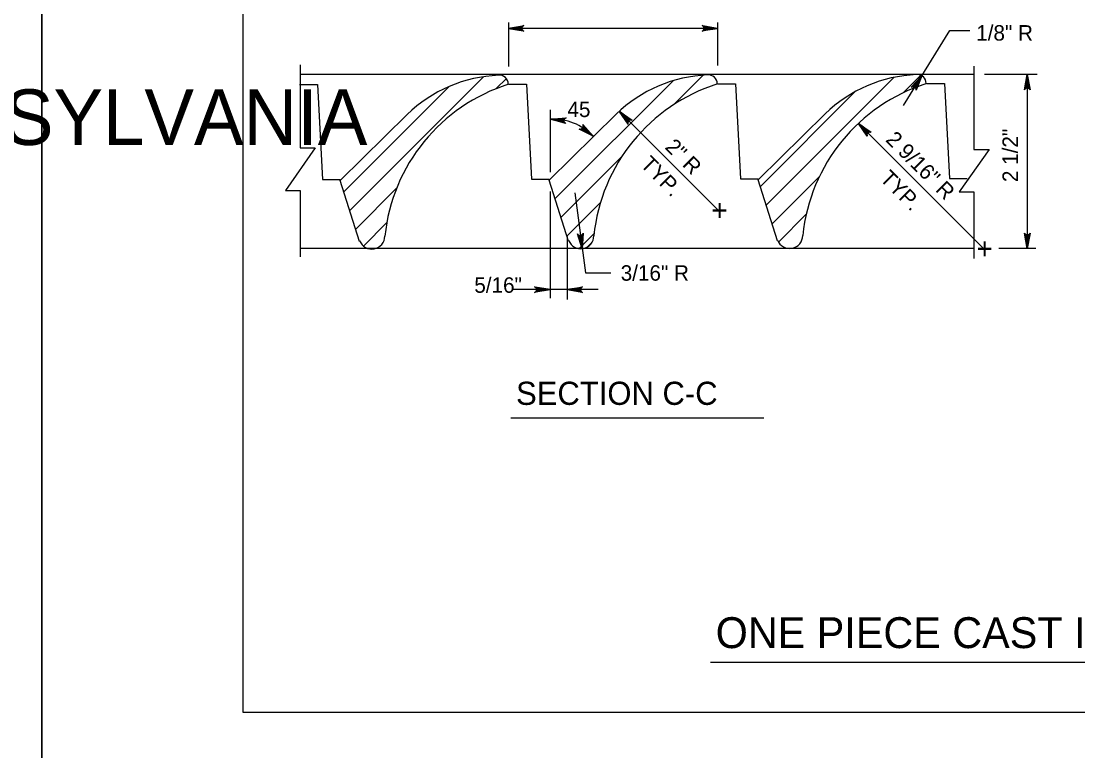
# Model space of a CAD drawing. Extents: x 2087776 to 2104538, y 970919 to 982612.
# Drawn here: x 2096040 to 2096713, y 976790 to 977255 of the extents above; entities that cross this region are included whole.
import ezdxf

# ---------------------------------------------------------------- set-up
doc = ezdxf.new("R2010")
doc.units = 0
doc.layers.add('1', color=7, linetype='Continuous')
doc.layers.add('PLT-BNDY', color=7, linetype='Continuous')

msp = doc.modelspace()

# ---------------------------------------------------------------- linework, layer by layer
at = {"layer": '1'}
for p, q in [((2096350.27, 977254.4), (2096350.27, 977226.29)), ((2096483.33, 977254.4), (2096483.33, 977226.92)), ((2096483.33, 977250.64), (2096350.27, 977250.64)), ((2096601.71, 977201.5), (2096631.33, 977249.24)), ((2096631.33, 977249.24), (2096644.03, 977249.24)), ((2096217.59, 977227.47), (2096217.59, 977174.47)), ((2096646.6, 977221.2), (2096217.59, 977221.2)), ((2096646.6, 977226.5), (2096646.6, 977173.5)), ((2096686.82, 977221.2), (2096653.44, 977221.2)), ((2096680.6, 977221.2), (2096680.6, 977110.47)), ((2096217.22, 977214.82), (2096228.75, 977214.82)), ((2096228.75, 977214.82), (2096231.93, 977154.35)), ((2096350.27, 977215.01), (2096361.81, 977215.03)), ((2096361.81, 977215.03), (2096364.99, 977154.55)), ((2096483.33, 977215.22), (2096494.86, 977215.22)), ((2096494.86, 977215.22), (2096498.05, 977154.76)), ((2096616.39, 977215.42), (2096627.91, 977215.43)), ((2096627.91, 977215.43), (2096631.1, 977154.96)), ((2096243.2, 977153.8), (2096285.8, 977195.79)), ((2096376.25, 977154), (2096418.85, 977196.01)), ((2096376.73, 977198.79), (2096376.73, 977158.95)), ((2096420.83, 977197.86), (2096483.79, 977134.89)), ((2096509.31, 977154.21), (2096551.9, 977196.21)), ((2096573.08, 977190.11), (2096652.26, 977110.93)), ((2096227.23, 977174.47), (2096208.21, 977147.38)), ((2096217.59, 977174.47), (2096227.23, 977174.47)), ((2096656.25, 977173.5), (2096637.23, 977146.42)), ((2096646.6, 977173.5), (2096656.25, 977173.5)), ((2096231.93, 977154.35), (2096243.2, 977154.35)), ((2096255.52, 977114.88), (2096243.2, 977153.8)), ((2096364.99, 977154.55), (2096376.25, 977154.55)), ((2096388.58, 977115.08), (2096376.25, 977154)), ((2096498.05, 977154.76), (2096509.31, 977154.76)), ((2096521.63, 977115.28), (2096509.31, 977154.21)), ((2096631.1, 977154.96), (2096642.37, 977154.96)), ((2096208.21, 977147.38), (2096217.59, 977147.38)), ((2096217.59, 977147.38), (2096217.59, 977105.07)), ((2096376.73, 977146.66), (2096376.73, 977078.76)), ((2096637.23, 977146.42), (2096646.6, 977146.42)), ((2096646.6, 977146.42), (2096646.6, 977104.11)), ((2096392.57, 977145.76), (2096399.29, 977094.93)), ((2096483.79, 977134.89), (2096483.79, 977134.89)), ((2096387.64, 977118.03), (2096387.64, 977077.86)), ((2096646.6, 977110.47), (2096217.59, 977110.47)), ((2096652.61, 977110.47), (2096652.61, 977110.47)), ((2096686, 977110.47), (2096662.49, 977110.47)), ((2096399.29, 977094.93), (2096415.46, 977094.93)), ((2096407.44, 977084.21), (2096352.36, 977084.21)), ((2096351.84, 977002.5), (2096512.91, 977002.5)), ((2096478.9, 976846.96), (2097073.31, 976846.96))]:
    msp.add_line(p, q, dxfattribs=at)
for points in [[(2098759.93, 976815.01), (2098759.93, 978665.4), (2096181.19, 978665.4), (2096181.19, 976815.01), (2098759.93, 976815.01), (2098759.93, 976901.49), (2098103.76, 976901.49), (2098103.76, 977113.68), (2098759.93, 977113.68), (2098759.93, 977208.71), (2098103.76, 977208.71), (2098103.76, 976815.01), (2098362.29, 976815.01), (2098362.29, 976901.49), (2098362.29, 976815.01), (2098614.92, 976815.01), (2098614.92, 976901.49), (2098614.92, 976861.08), (2098759.93, 976861.08)], [(2096350.27, 977250.64), (2096360.06, 977252.47), (2096359.68, 977252.21), (2096359.3, 977251.95), (2096359.11, 977251.62), (2096358.91, 977251.29), (2096358.86, 977250.97), (2096358.8, 977250.64), (2096358.86, 977250.31), (2096358.91, 977249.98), (2096359.11, 977249.65), (2096359.3, 977249.33), (2096359.68, 977249.06), (2096360.06, 977248.8), (2096350.27, 977250.64), (2096359.68, 977249.06), (2096359.3, 977249.33), (2096350.27, 977250.64), (2096359.11, 977249.65), (2096358.91, 977249.98), (2096350.27, 977250.64), (2096358.86, 977250.31), (2096358.8, 977250.64), (2096350.27, 977250.64), (2096358.86, 977250.97), (2096358.91, 977251.29), (2096350.27, 977250.64), (2096359.11, 977251.62), (2096359.3, 977251.95), (2096350.27, 977250.64), (2096359.68, 977252.21)], [(2096483.33, 977250.64), (2096473.55, 977248.8), (2096473.93, 977249.06), (2096474.3, 977249.33), (2096474.5, 977249.65), (2096474.69, 977249.98), (2096474.75, 977250.31), (2096474.8, 977250.64), (2096474.75, 977250.97), (2096474.69, 977251.29), (2096474.5, 977251.62), (2096474.3, 977251.95), (2096473.93, 977252.21), (2096473.55, 977252.47), (2096483.33, 977250.64), (2096473.93, 977252.21), (2096474.3, 977251.95), (2096483.33, 977250.64), (2096474.5, 977251.62), (2096474.69, 977251.29), (2096483.33, 977250.64), (2096474.75, 977250.97), (2096474.8, 977250.64), (2096483.33, 977250.64), (2096474.75, 977250.31), (2096474.69, 977249.98), (2096483.33, 977250.64), (2096474.5, 977249.65), (2096474.3, 977249.33), (2096483.33, 977250.64), (2096473.93, 977249.06)], [(2096455.63, 977202.11), (2096474.32, 977220.81)], [(2096601.48, 977209.52), (2096612.75, 977220.79)], [(2096613.46, 977220.44), (2096609.86, 977211.16), (2096609.84, 977211.61), (2096609.82, 977212.07), (2096609.64, 977212.41), (2096609.46, 977212.75), (2096609.21, 977212.97), (2096608.96, 977213.19), (2096608.66, 977213.32), (2096608.35, 977213.44), (2096607.97, 977213.45), (2096607.59, 977213.46), (2096607.16, 977213.27), (2096606.74, 977213.09), (2096613.46, 977220.44), (2096607.16, 977213.27), (2096607.59, 977213.46), (2096613.46, 977220.44), (2096607.97, 977213.45), (2096608.35, 977213.44), (2096613.46, 977220.44), (2096608.66, 977213.32), (2096608.96, 977213.19), (2096613.46, 977220.44), (2096609.21, 977212.97), (2096609.46, 977212.75), (2096613.46, 977220.44), (2096609.64, 977212.41), (2096609.82, 977212.07), (2096613.46, 977220.44), (2096609.84, 977211.61)], [(2096680.6, 977221.2), (2096682.43, 977211.41), (2096682.17, 977211.79), (2096681.91, 977212.16), (2096681.58, 977212.36), (2096681.25, 977212.55), (2096680.93, 977212.61), (2096680.6, 977212.67), (2096680.27, 977212.61), (2096679.94, 977212.55), (2096679.61, 977212.36), (2096679.29, 977212.16), (2096679.02, 977211.79), (2096678.76, 977211.41), (2096680.6, 977221.2), (2096679.02, 977211.79), (2096679.29, 977212.16), (2096680.6, 977221.2), (2096679.61, 977212.36), (2096679.94, 977212.55), (2096680.6, 977221.2), (2096680.27, 977212.61), (2096680.6, 977212.67), (2096680.6, 977221.2), (2096680.93, 977212.61), (2096681.25, 977212.55), (2096680.6, 977221.2), (2096681.58, 977212.36), (2096681.91, 977212.16), (2096680.6, 977221.2), (2096682.17, 977211.79)], [(2096245.49, 977146.58), (2096312.55, 977213.63)], [(2096249.26, 977134.67), (2096334.42, 977219.85)], [(2096342.45, 977212.22), (2096348.91, 977218.67)], [(2096380.01, 977142.15), (2096455.16, 977217.3)], [(2096514.4, 977138.1), (2096595.7, 977219.4)], [(2096510.64, 977150), (2096570.89, 977210.24)], [(2096377.05, 977192.71), (2096386.95, 977193.73), (2096386.56, 977193.5), (2096386.16, 977193.27), (2096385.94, 977192.96), (2096385.72, 977192.65), (2096385.64, 977192.33), (2096385.55, 977192.01), (2096385.58, 977191.67), (2096385.61, 977191.34), (2096385.78, 977191), (2096385.94, 977190.66), (2096386.3, 977190.37), (2096386.65, 977190.07), (2096377.05, 977192.71), (2096386.3, 977190.37), (2096385.94, 977190.66), (2096377.05, 977192.71), (2096385.78, 977191), (2096385.61, 977191.34), (2096377.05, 977192.71), (2096385.58, 977191.67), (2096385.55, 977192.01), (2096377.05, 977192.71), (2096385.64, 977192.33), (2096385.72, 977192.65), (2096377.05, 977192.71), (2096385.94, 977192.96), (2096386.16, 977193.27), (2096377.05, 977192.71), (2096386.56, 977193.5)], [(2096420.83, 977197.86), (2096429.04, 977192.24), (2096428.59, 977192.32), (2096428.14, 977192.4), (2096427.77, 977192.31), (2096427.4, 977192.21), (2096427.13, 977192.02), (2096426.86, 977191.83), (2096426.67, 977191.56), (2096426.47, 977191.29), (2096426.38, 977190.92), (2096426.29, 977190.55), (2096426.37, 977190.1), (2096426.45, 977189.64), (2096420.83, 977197.86), (2096426.37, 977190.1), (2096426.29, 977190.55), (2096420.83, 977197.86), (2096426.38, 977190.92), (2096426.47, 977191.29), (2096420.83, 977197.86), (2096426.67, 977191.56), (2096426.86, 977191.83), (2096420.83, 977197.86), (2096427.13, 977192.02), (2096427.4, 977192.21), (2096420.83, 977197.86), (2096427.77, 977192.31), (2096428.14, 977192.4), (2096420.83, 977197.86), (2096428.59, 977192.32)], [(2096404.21, 977181.97), (2096395.35, 977186.52), (2096395.81, 977186.49), (2096396.27, 977186.47), (2096396.62, 977186.61), (2096396.98, 977186.75), (2096397.22, 977186.97), (2096397.47, 977187.2), (2096397.63, 977187.49), (2096397.78, 977187.79), (2096397.83, 977188.17), (2096397.88, 977188.54), (2096397.74, 977188.98), (2096397.6, 977189.42), (2096404.21, 977181.97), (2096397.74, 977188.98), (2096397.88, 977188.54), (2096404.21, 977181.97), (2096397.83, 977188.17), (2096397.78, 977187.79), (2096404.21, 977181.97), (2096397.63, 977187.49), (2096397.47, 977187.2), (2096404.21, 977181.97), (2096397.22, 977186.97), (2096396.98, 977186.75), (2096404.21, 977181.97), (2096396.62, 977186.61), (2096396.27, 977186.47), (2096404.21, 977181.97), (2096395.81, 977186.49)], [(2096573.08, 977190.11), (2096581.3, 977184.48), (2096580.85, 977184.57), (2096580.4, 977184.65), (2096580.03, 977184.55), (2096579.66, 977184.46), (2096579.39, 977184.27), (2096579.12, 977184.07), (2096578.92, 977183.8), (2096578.73, 977183.53), (2096578.64, 977183.16), (2096578.54, 977182.79), (2096578.62, 977182.34), (2096578.71, 977181.89), (2096573.08, 977190.11), (2096578.62, 977182.34), (2096578.54, 977182.79), (2096573.08, 977190.11), (2096578.64, 977183.16), (2096578.73, 977183.53), (2096573.08, 977190.11), (2096578.92, 977183.8), (2096579.12, 977184.07), (2096573.08, 977190.11), (2096579.39, 977184.27), (2096579.66, 977184.46), (2096573.08, 977190.11), (2096580.03, 977184.55), (2096580.4, 977184.65), (2096573.08, 977190.11), (2096580.85, 977184.57)], [(2096383.77, 977130.26), (2096422.44, 977168.93)], [(2096518.17, 977126.21), (2096548.3, 977156.33)], [(2096253.02, 977122.78), (2096279.08, 977148.84)], [(2096387.53, 977118.36), (2096408.87, 977139.69)], [(2096257.87, 977111.97), (2096272.8, 977126.9)], [(2096522.17, 977114.54), (2096539.92, 977132.29)], [(2096397.27, 977110.25), (2096394.17, 977119.72), (2096394.47, 977119.38), (2096394.78, 977119.04), (2096395.13, 977118.89), (2096395.48, 977118.74), (2096395.82, 977118.72), (2096396.15, 977118.71), (2096396.47, 977118.81), (2096396.78, 977118.91), (2096397.08, 977119.14), (2096397.38, 977119.38), (2096397.59, 977119.79), (2096397.8, 977120.2), (2096397.27, 977110.25), (2096397.59, 977119.79), (2096397.38, 977119.38), (2096397.27, 977110.25), (2096397.08, 977119.14), (2096396.78, 977118.91), (2096397.27, 977110.25), (2096396.47, 977118.81), (2096396.15, 977118.71), (2096397.27, 977110.25), (2096395.82, 977118.72), (2096395.48, 977118.74), (2096397.27, 977110.25), (2096395.13, 977118.89), (2096394.78, 977119.04), (2096397.27, 977110.25), (2096394.47, 977119.38)], [(2096395.12, 977110.29), (2096404.8, 977119.97)], [(2096680.6, 977110.47), (2096678.76, 977120.25), (2096679.02, 977119.88), (2096679.29, 977119.5), (2096679.61, 977119.3), (2096679.94, 977119.11), (2096680.27, 977119.05), (2096680.6, 977119), (2096680.93, 977119.05), (2096681.25, 977119.11), (2096681.58, 977119.3), (2096681.91, 977119.5), (2096682.17, 977119.88), (2096682.43, 977120.25), (2096680.6, 977110.47), (2096682.17, 977119.88), (2096681.91, 977119.5), (2096680.6, 977110.47), (2096681.58, 977119.3), (2096681.25, 977119.11), (2096680.6, 977110.47), (2096680.93, 977119.05), (2096680.6, 977119), (2096680.6, 977110.47), (2096680.27, 977119.05), (2096679.94, 977119.11), (2096680.6, 977110.47), (2096679.61, 977119.3), (2096679.29, 977119.5), (2096680.6, 977110.47), (2096679.02, 977119.88)], [(2096388.56, 977115.13), (2096388.58, 977115.14)], [(2096403.54, 977114.45), (2096400.35, 977111.26)], [(2096376.73, 977084.21), (2096366.94, 977082.37), (2096367.32, 977082.63), (2096367.7, 977082.89), (2096367.89, 977083.22), (2096368.08, 977083.55), (2096368.14, 977083.88), (2096368.2, 977084.21), (2096368.14, 977084.54), (2096368.08, 977084.86), (2096367.89, 977085.19), (2096367.7, 977085.52), (2096367.32, 977085.78), (2096366.94, 977086.04), (2096376.73, 977084.21), (2096367.32, 977085.78), (2096367.7, 977085.52), (2096376.73, 977084.21), (2096367.89, 977085.19), (2096368.08, 977084.86), (2096376.73, 977084.21), (2096368.14, 977084.54), (2096368.2, 977084.21), (2096376.73, 977084.21), (2096368.14, 977083.88), (2096368.08, 977083.55), (2096376.73, 977084.21), (2096367.89, 977083.22), (2096367.7, 977082.89), (2096376.73, 977084.21), (2096367.32, 977082.63)], [(2096387.64, 977084.21), (2096397.42, 977086.04), (2096397.05, 977085.78), (2096396.67, 977085.52), (2096396.48, 977085.19), (2096396.28, 977084.86), (2096396.23, 977084.54), (2096396.17, 977084.21), (2096396.23, 977083.88), (2096396.28, 977083.55), (2096396.48, 977083.22), (2096396.67, 977082.89), (2096397.05, 977082.63), (2096397.42, 977082.37), (2096387.64, 977084.21), (2096397.05, 977082.63), (2096396.67, 977082.89), (2096387.64, 977084.21), (2096396.48, 977083.22), (2096396.28, 977083.55), (2096387.64, 977084.21), (2096396.23, 977083.88), (2096396.17, 977084.21), (2096387.64, 977084.21), (2096396.23, 977084.54), (2096396.28, 977084.86), (2096387.64, 977084.21), (2096396.48, 977085.19), (2096396.67, 977085.52), (2096387.64, 977084.21), (2096397.05, 977085.78)]]:
    msp.add_lwpolyline(points, dxfattribs=at)
for centre, radius, start, end in [((2096347.5, 977132.24), 88.58, 92.2408, 134.15119), ((2096344.55, 977215.25), 5.54, 358.80842, 95.60113), ((2096480.56, 977132.45), 88.58, 92.2408, 134.15119), ((2096477.61, 977215.46), 5.54, 358.80842, 95.60113), ((2096613.61, 977132.65), 88.58, 92.2408, 134.15119), ((2096610.67, 977215.66), 5.54, 358.80842, 95.60113), ((2096384.5, 977106.8), 113.5, 107.54824, 174.17661), ((2096517.55, 977107), 113.5, 107.54824, 174.17661), ((2096650.61, 977107.21), 113.5, 107.54824, 174.17661), ((2096378.63, 977156.97), 35.77, 44.34129, 92.52783), ((2096263.24, 977118.3), 8.3, 201.52901, 0.12164), ((2096396.3, 977118.5), 8.3, 201.52901, 0.12164), ((2096529.35, 977118.71), 8.3, 201.52901, 0.12164)]:
    msp.add_arc(centre, radius, start, end, dxfattribs=at)
at = {"layer": 'PLT-BNDY'}
for points in [[(2093294.05, 978714.61), (2096053.23, 978714.61), (2096053.23, 976765.79), (2093294.05, 976765.79)], [(2096053.23, 978714.61), (2098812.42, 978714.61), (2098812.42, 976765.79), (2096053.23, 976765.79)]]:
    msp.add_lwpolyline(points, close=True, dxfattribs=at)

# ---------------------------------------------------------------- texts
at = {"layer": '1'}
for s, height, p in [('1/8" R', 9.843, (2096648.1, 977242.83)), ('COMMONWEALTH OF PENNSYLVANIA', 35.3785, (2095387.72, 977176.37)), ('45', 9.843, (2096387.82, 977194.13)), ('+', 13.29, (2096479.52, 977128.17)), ('+', 13.29, (2096648.29, 977103.77)), ('3/16" R', 9.843, (2096421.73, 977089.9)), ('5/16"', 9.843, (2096328.52, 977082.19)), ('SECTION C-C', 14.7638, (2096355.1, 977010.79)), ('ONE PIECE CAST IRON VANE GRATE', 19.685, (2096482.21, 976855.86))]:
    msp.add_text(s, height=height, dxfattribs=at).set_placement(p)
for s, rotation, p in [('2 9/16" R', 315, (2096589.92, 977179.16)), ('2 1/2"', 90, (2096674.65, 977152.73)), ('2" R', 315, (2096449.36, 977174.4)), ('TYP.', 315, (2096433.79, 977163.35)), ('TYP.', 315, (2096586.26, 977154.31))]:
    msp.add_text(s, height=9.843, rotation=rotation, dxfattribs=at).set_placement(p)

doc.saveas('drawing.dxf')
